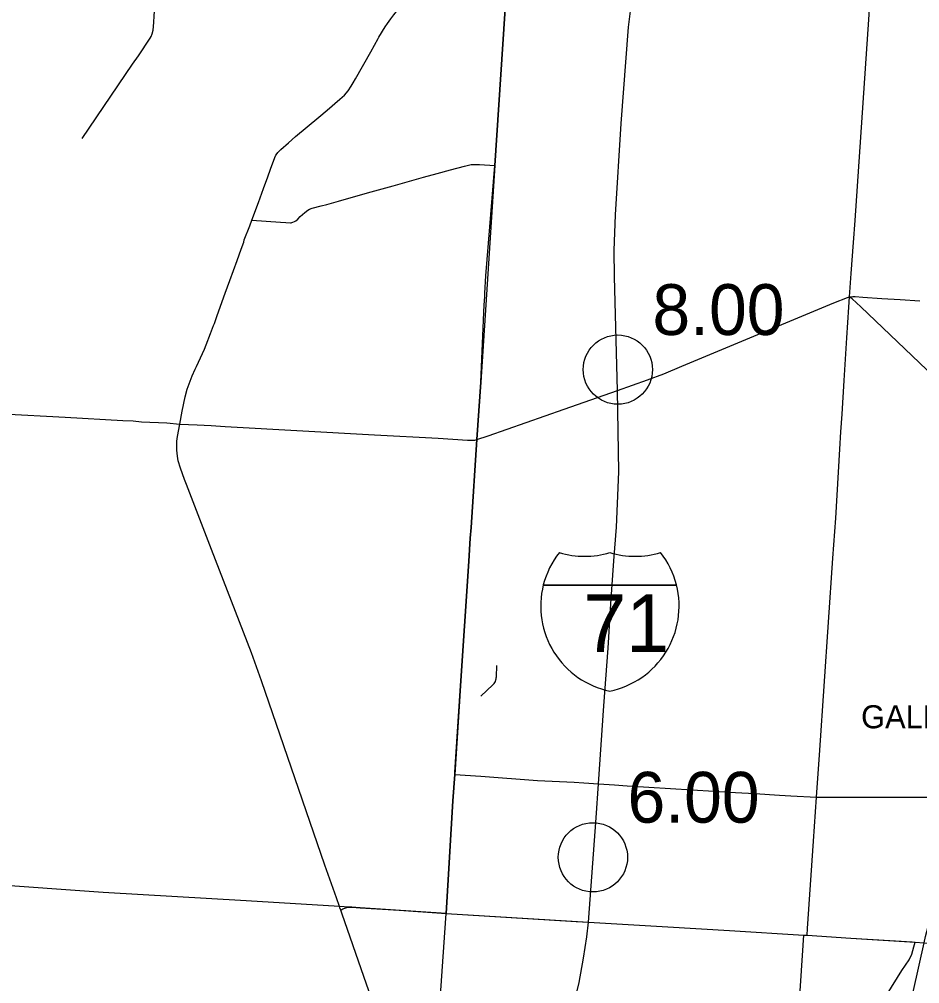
# Model space of a CAD drawing. Extents: x 1729596 to 1934326, y 644115 to 911751.
# Drawn here: x 1835895 to 1855413, y 803658 to 824548 of the extents above; entities that cross this region are included whole.
import ezdxf

# ---------------------------------------------------------------- set-up
doc = ezdxf.new("R2010")
doc.units = 0
for name, color, linetype in [('Default', 7, 'Continuous'), ('GM_X_Corporation_Text', 7, 'Continuous'), ('GM_X_County_Road', 7, 'Continuous'), ('GM_X_Interstate_Route', 7, 'Continuous'), ('GM_X_Interstate_Shield', 7, 'Continuous'), ('GM_X_State_Route', 7, 'Continuous'), ('GM_X_Township', 7, 'Continuous'), ('GM_X_Township_Road', 7, 'Continuous')]:
    doc.layers.add(name, color=color, linetype=linetype)

msp = doc.modelspace()

# ---------------------------------------------------------------- linework, layer by layer
at = {"layer": 'Default'}
for centre in [(1848869, 816960), (1848329, 806396)]:
    msp.add_circle(centre, 750, dxfattribs=at)
at = {"layer": 'GM_X_County_Road'}
for points in [[(1837255, 821964), (1838352, 823573), (1838477, 823753), (1838734, 824138), (1838754, 824176), (1838776, 824230), (1838797, 824315), (1838813, 824478), (1838822, 824624), (1838961, 826468), (1838996, 826913), (1839038, 827452), (1839065, 827768), (1839090, 828131)], [(1843676, 824135), (1843691, 824163), (1843825, 824382), (1843877, 824459), (1843910, 824506), (1843948, 824557), (1844017, 824645), (1844192, 824870), (1844248, 824955), (1844313, 825075), (1844345, 825149), (1844376, 825251), (1844395, 825340), (1844404, 825395), (1844424, 825605), (1844428, 825666)], [(1853892, 818538), (1853927, 819045), (1853979, 819713), (1854011, 820193), (1854357, 825298), (1854354, 825422)], [(1840108, 817915), (1840125, 817960), (1840185, 818129), (1840360, 818619), (1840456, 818888), (1840615, 819321), (1840707, 819568), (1840763, 819722), (1840773, 819774), (1840889, 820072), (1840934, 820196), (1841077, 820583), (1841186, 820882), (1841282, 821134), (1841343, 821301), (1841435, 821553), (1841459, 821602), (1841482, 821642), (1841498, 821666), (1841562, 821727), (1841728, 821872), (1841885, 822009), (1842387, 822426), (1842567, 822583), (1842842, 822816), (1842945, 822908), (1843026, 822996), (1843091, 823097), (1843134, 823175), (1843183, 823260), (1843512, 823845), (1843676, 824135)], [(1845813, 815443), (1846057, 815523), (1847704, 816100), (1848860, 816509), (1849512, 816739), (1849867, 816870), (1850255, 817032), (1853548, 818404), (1853845, 818524), (1853892, 818538)], [(1852972, 804706), (1852981, 804856), (1853110, 806745), (1853175, 807697), (1853246, 808714), (1853530, 812876), (1853592, 813742), (1853681, 815234), (1853705, 815613), (1853731, 815995), (1853772, 816725), (1853832, 817646), (1853875, 818312), (1853892, 818538)], [(1853892, 818538), (1853963, 818545), (1854011, 818543), (1854178, 818529), (1854595, 818503), (1854991, 818481), (1855415, 818448)], [(1857182, 815299), (1857153, 815378), (1857124, 815436), (1857089, 815491), (1857039, 815553), (1856865, 815727), (1856650, 815933), (1856316, 816250), (1855886, 816655), (1854135, 818318), (1853948, 818496), (1853892, 818538)], [(1839372, 815780), (1839425, 816059), (1839488, 816370), (1839533, 816537), (1839646, 816828), (1839707, 816968), (1839735, 817030), (1839908, 817404), (1839909, 817406), (1839949, 817498), (1840041, 817739), (1840108, 817915)], [(1831958, 816015), (1832323, 815989), (1832460, 815979), (1832837, 815953), (1832930, 815950), (1833024, 815953), (1833112, 815962), (1833413, 816008), (1833762, 816064), (1833870, 816076), (1833979, 816082), (1834125, 816080), (1834617, 816051), (1834676, 816048), (1834735, 816046), (1835535, 816000), (1836888, 815933), (1838141, 815859), (1838366, 815848), (1838544, 815828), (1839093, 815806), (1839372, 815780)], [(1842846, 805301), (1842837, 805328), (1842772, 805518), (1842519, 806229), (1841146, 810217), (1840928, 810827), (1840065, 813066), (1839518, 814468), (1839479, 814577), (1839387, 814825), (1839342, 814985), (1839324, 815084), (1839310, 815214), (1839307, 815315), (1839311, 815371), (1839312, 815408), (1839319, 815463), (1839325, 815513), (1839372, 815780)], [(1839372, 815780), (1839750, 815761), (1840057, 815746), (1840358, 815730), (1843594, 815549), (1844974, 815476), (1845607, 815434), (1845771, 815433), (1845813, 815443)], [(1843910, 802243), (1843360, 803811), (1842894, 805162), (1842863, 805251), (1842846, 805301)], [(1852657, 800886), (1852657, 800961), (1852774, 802805), (1852798, 803172), (1852898, 804710), (1852972, 804706)]]:
    msp.add_lwpolyline(points, dxfattribs=at)
at = {"layer": 'GM_X_Interstate_Route'}
msp.add_lwpolyline([(1847964, 803419), (1848028, 803685), (1848125, 804211), (1848200, 804670), (1848231, 804991), (1848401, 807248), (1848453, 807987), (1848565, 809674), (1848656, 810925), (1848716, 811884), (1848786, 812818), (1848839, 813548), (1848865, 814059), (1848894, 814749), (1848860, 816509), (1848794, 818972), (1848791, 819542), (1848815, 820309), (1848943, 822290), (1849103, 824378), (1849147, 824725), (1849232, 825823)], dxfattribs=at)
at = {"layer": 'GM_X_Interstate_Shield'}
for p, q in [((1847254, 812294), (1850140, 812294)), ((1850140, 812294), (1847254, 812294)), ((1850140, 812294), (1847254, 812294)), ((1847254, 812294), (1850140, 812294)), ((1850140, 812294), (1847254, 812294)), ((1850140, 812294), (1847254, 812294))]:
    msp.add_line(p, q, dxfattribs=at)
for centre, start, end in [((1849072, 811835), 141.669, 165.8066), ((1849072, 811835), 141.669, 165.8066), ((1848149, 814791), 253.0091, 286.9909), ((1848149, 814791), 253.0091, 286.9909), ((1849245, 814791), 253.0091, 286.9909), ((1849245, 814791), 253.0091, 286.9909), ((1848322, 811835), 14.1934, 38.331), ((1848322, 811835), 14.1934, 38.331), ((1849072, 811835), 165.8066, 258.463), ((1849072, 811835), 165.8066, 258.463), ((1848322, 811835), 281.537, 14.1934), ((1848322, 811835), 281.537, 14.1934)]:
    msp.add_arc(centre, 1875, start, end, dxfattribs=at)
at = {"layer": 'GM_X_State_Route'}
msp.add_lwpolyline([(1853225, 794338), (1854573, 800349), (1855512, 804546), (1855541, 804679), (1855596, 804898), (1855689, 805139), (1855836, 805465), (1855908, 805599), (1856008, 805767), (1856148, 805978), (1856255, 806119), (1856504, 806413), (1857597, 807668), (1858467, 808668), (1858818, 809072), (1859440, 809788), (1860025, 810459)], dxfattribs=at)
at = {"layer": 'GM_X_Township'}
for points in [[(1846509, 825988), (1846205, 821378), (1845900, 816686), (1845813, 815443), (1845687, 813540), (1845670, 813309), (1845637, 812811), (1845452, 810003), (1845333, 808188), (1845296, 807619), (1845145, 805182), (1843287, 805303), (1843103, 805315), (1843041, 805313), (1842837, 805328), (1840812, 805456), (1837716, 805633), (1832763, 805986)], [(1844785, 799970), (1845145, 805182), (1848231, 804991), (1849953, 804892), (1851286, 804810), (1852898, 804710), (1852972, 804706), (1853920, 804647), (1855314, 804559), (1855512, 804546), (1855904, 804520), (1856177, 804502), (1856300, 804491), (1856579, 804475), (1858107, 804378), (1864561, 803926), (1870008, 803514)]]:
    msp.add_lwpolyline(points, dxfattribs=at)
at = {"layer": 'GM_X_Township_Road'}
for points in [[(1846205, 821378), (1846509, 825988)], [(1840934, 820196), (1841554, 820152), (1841675, 820144), (1841771, 820139), (1841789, 820141), (1841806, 820145), (1841824, 820150), (1841857, 820165), (1841886, 820186), (1841932, 820222), (1841987, 820273), (1842088, 820362), (1842150, 820411), (1842188, 820437), (1842243, 820457), (1842436, 820506), (1842558, 820533), (1842815, 820608), (1843441, 820786), (1843996, 820944), (1844660, 821131), (1844951, 821209), (1845239, 821285), (1845542, 821368), (1845693, 821404), (1845774, 821406), (1845873, 821404), (1846205, 821378)], [(1845813, 815443), (1845900, 816686), (1845973, 818365), (1845978, 818443), (1845984, 818548), (1845988, 818619), (1846010, 818988), (1846205, 821378)], [(1845336, 808240), (1845452, 810003), (1845637, 812811), (1845670, 813309), (1845687, 813540), (1845813, 815443)], [(1845901, 809883), (1846157, 810131), (1846187, 810162), (1846202, 810185), (1846214, 810206), (1846226, 810238), (1846229, 810261), (1846233, 810284), (1846236, 810308), (1846248, 810548)], [(1845145, 805182), (1845296, 807619), (1845333, 808188), (1845336, 808240)], [(1845333, 808188), (1845902, 808151), (1847128, 808058), (1847922, 808022), (1848130, 808008), (1848453, 807987), (1848798, 807964), (1849069, 807946), (1851423, 807800), (1851838, 807775), (1852372, 807742), (1852621, 807728), (1853175, 807697)], [(1853175, 807697), (1854218, 807699), (1855651, 807697), (1856991, 807682), (1857244, 807678), (1857423, 807675), (1857597, 807668)], [(1842863, 805251), (1842909, 805278), (1842951, 805293), (1842996, 805306), (1843041, 805313), (1843065, 805314)], [(1843065, 805314), (1843103, 805315), (1843287, 805303), (1844132, 805248)], [(1844132, 805248), (1845145, 805182)], [(1845145, 805182), (1847965, 805008)], [(1847965, 805008), (1848231, 804991), (1849953, 804892), (1851286, 804810), (1852898, 804710)], [(1852972, 804706), (1853920, 804647), (1855248, 804563)], [(1853063, 800779), (1853085, 800818), (1853124, 800877), (1853467, 801413), (1853904, 802110), (1854482, 803071), (1855027, 803947), (1855187, 804174), (1855245, 804296), (1855285, 804458), (1855314, 804559)], [(1855248, 804563), (1855314, 804559), (1855512, 804546)]]:
    msp.add_lwpolyline(points, dxfattribs=at)

# ---------------------------------------------------------------- texts
at = {"layer": 'Default'}
for s, p in [('8.00', (1849619, 817710)), ('6.00', (1849079, 807146))]:
    msp.add_text(s, height=1100, dxfattribs=at).set_placement(p)
at = {"layer": 'GM_X_Corporation_Text'}
msp.add_text('GALENA', height=500, rotation=0, dxfattribs=at).set_placement((1854142, 809190))
at = {"layer": 'GM_X_Interstate_Shield'}
msp.add_text('71', height=1250, dxfattribs=at).set_placement((1848119, 810841))
msp.add_text('71', height=1250, dxfattribs=at).set_placement((1848119, 810841))

doc.saveas('drawing.dxf')
